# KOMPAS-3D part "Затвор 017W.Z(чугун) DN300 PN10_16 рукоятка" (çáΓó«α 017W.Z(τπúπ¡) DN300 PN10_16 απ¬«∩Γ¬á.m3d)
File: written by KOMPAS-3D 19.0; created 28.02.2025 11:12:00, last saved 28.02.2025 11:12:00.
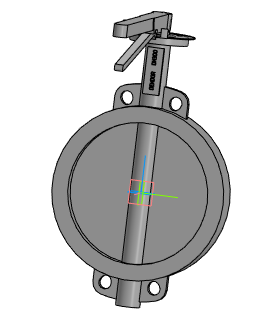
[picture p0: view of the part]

Document properties: Автор: Евгений; Полное имя файла: Затвор 017W.Z(чугун) DN300 PN10_16 рукоятка.a3d

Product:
- Part/product: Затвор 017W.Z(чугун) DN300 PN10_16 рукоятка
    Масса: 46.184

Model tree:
1. Операция без истории:1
